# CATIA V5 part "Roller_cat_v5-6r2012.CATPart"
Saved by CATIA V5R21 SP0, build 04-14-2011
Part number: Roller
Bounding box of the stored display mesh (mm): x 0 to 20, y -10 to 10, z -10 to 10
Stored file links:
  D:\CATIA V5R21 E-RESOURCES\CATIA-V5R21\catia-v5r21-Tut\c16-catia-v5r21-tut\c16-catia-v5r21-tut04\Roller_cat_v5r21.CATPart
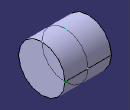
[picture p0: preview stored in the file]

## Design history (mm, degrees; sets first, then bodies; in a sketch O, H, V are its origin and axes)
Body1 (main body)
  Sketch1 on yz-plane, origin (0, 0, 0), H (0, 1, 0), V (0, 0, 1)
    circle A1 centre (0, 0) radius 10
    radius A1 = 10
  Pad1: profile Sketch1, direction (1, 0, 0), length 20
  Plane1: type Offset, RefPlane end face of Pad1, Offset -10, reversed
  Sketch2 on Plane1, origin (10, 0, 0), H (0, -1, 0), V (0, 0, 1)
    projected circle E1 centre (0, 0) radius 10 from edge [face of Pad1 from Sketch1.A1 | end face of Pad1]
    point P1 (0, -10)
    point P2 (0, 10)
    coincidence: P1 E1, P1 V, P2 V, E1 P2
